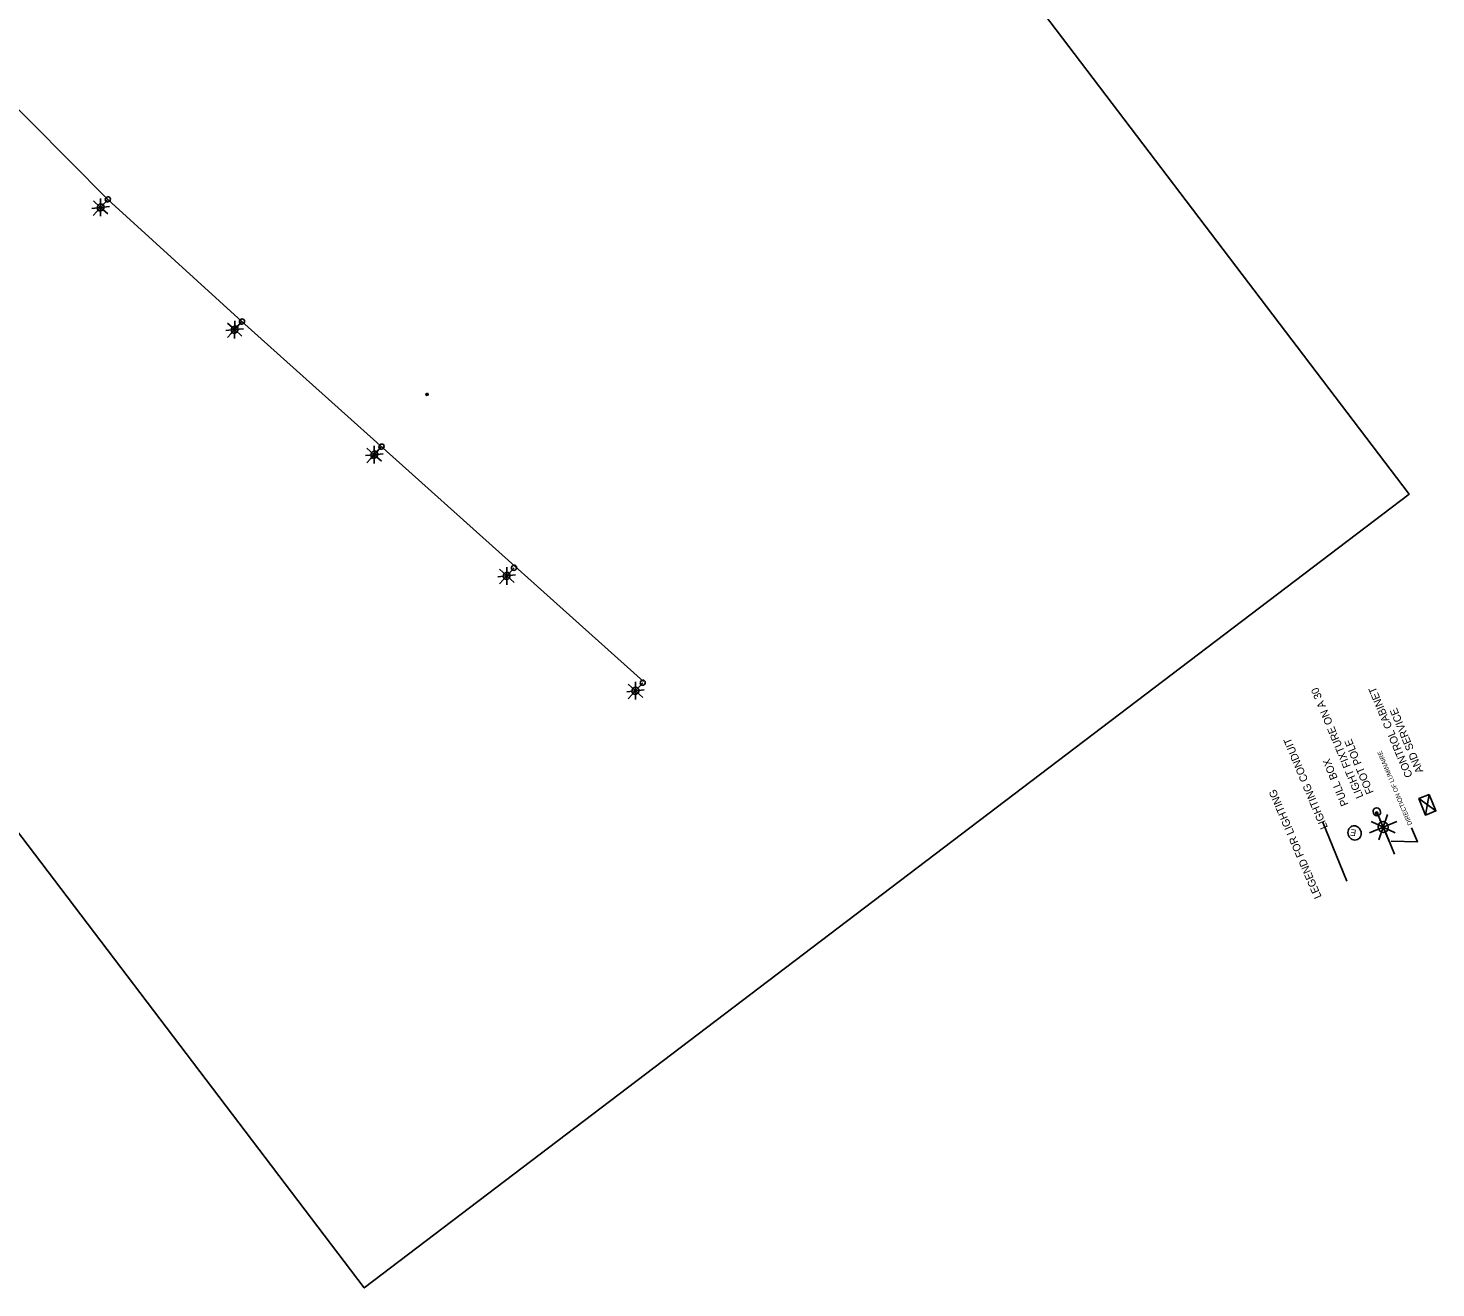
# Model space of a CAD drawing. Extents: x 1111012 to 1112403, y 616518 to 619149.
# Drawn here: x 1111840 to 1112403, y 616518 to 617023 of the extents above; entities that cross this region are included whole.
import ezdxf

# ---------------------------------------------------------------- set-up
doc = ezdxf.new("R2010")
doc.units = 0
for name, color, linetype in [('VSL-BACKGROUND', 7, 'Continuous'), ('VSL-CALCULATIONVALUES', 7, 'Continuous'), ('VSL-CONTOURS', 7, 'Continuous'), ('VSL-LUMINAIRES', 7, 'Continuous'), ('VSL-POWERZONES', 7, 'Continuous'), ('VSL-SOLIDS', 7, 'Continuous'), ('VSL-TEMPLATES', 7, 'Continuous')]:
    doc.layers.add(name, color=color, linetype=linetype)

msp = doc.modelspace()

# ---------------------------------------------------------------- linework, layer by layer
at = {"layer": 'VSL-BACKGROUND'}
msp.add_lwpolyline([(1111938.48, 617433.19), (1112392.16, 616835.98), (1111974.11, 616518.4), (1111520.42, 617115.61)], close=True, dxfattribs=at)
at = {"layer": 'VSL-CALCULATIONVALUES'}
msp.add_lwpolyline([(1112393.1, 616702.52), (1112395.46, 616696.88), (1112385, 616697.15)], dxfattribs=at)
at = {"layer": 'VSL-CONTOURS'}
msp.add_line((1112367.25, 616681.12), (1112357.47, 616704.99), dxfattribs=at)
at = {"layer": 'VSL-LUMINAIRES'}
msp.add_ellipse((1112370.34, 616700.47), major_axis=(1.11, -2.66), ratio=0.901044, dxfattribs=at)
at = {"layer": 'VSL-POWERZONES'}
for points in [[(1111999.39, 616876.47), (1111998.74, 616876.17), (1111999.06, 616875.48), (1111999.72, 616875.78)], [(1111999.39, 616876.47), (1111998.74, 616876.17), (1111999.06, 616875.48), (1111999.72, 616875.78)], [(1112379.33, 616708.93), (1112378.67, 616708.63), (1112379, 616707.95), (1112379.65, 616708.24)], [(1112379.33, 616708.93), (1112378.67, 616708.63), (1112379, 616707.95), (1112379.65, 616708.24)]]:
    msp.add_lwpolyline(points, close=True, dxfattribs=at)
for points in [[(1111999.29, 616876.43), (1111999.29, 616876.43)], [(1112379.23, 616708.89), (1112379.23, 616708.89)]]:
    msp.add_lwpolyline(points, dxfattribs=at)
at = {"layer": 'VSL-SOLIDS'}
for p, q in [((1112402.85, 616709.29), (1112396.09, 616714.19)), ((1112400.23, 616715.84), (1112398.71, 616707.63)), ((1112379.23, 616708.89), (1112381.77, 616702.81)), ((1112381.77, 616702.81), (1112383.54, 616707.86)), ((1112381.77, 616702.81), (1112376.29, 616700.52)), ((1112381.77, 616702.81), (1112376.94, 616705.1)), ((1112381.77, 616702.81), (1112380, 616697.76)), ((1112381.77, 616702.81), (1112387.24, 616705.1)), ((1112381.77, 616702.81), (1112384.31, 616696.73)), ((1112381.77, 616702.81), (1112386.6, 616700.52))]:
    msp.add_line(p, q, dxfattribs=at)
msp.add_lwpolyline([(1112400.23, 616715.84), (1112402.85, 616709.29), (1112398.71, 616707.63), (1112396.09, 616714.19)], close=True, dxfattribs=at)
msp.add_lwpolyline([(1112380.5, 616705.85), (1112383.04, 616699.77), (1112386.3, 616691.96)], dxfattribs=at)
for centre, major_axis in [((1112379.24, 616708.9), (-0.63, 1.52)), ((1112381.77, 616702.81), (-0.86, 2.08))]:
    msp.add_ellipse(centre, major_axis=major_axis, ratio=0.899857, dxfattribs=at)
at = {"layer": 'VSL-TEMPLATES'}
for p, q in [((1111868.61, 616950.79), (1111865.09, 616950.42)), ((1111868.61, 616950.79), (1111865.69, 616947.56)), ((1111868.61, 616950.79), (1111865.7, 616953.41)), ((1111870.06, 616952.41), (1111867.15, 616949.18)), ((1111868.61, 616950.79), (1111868.6, 616947.26)), ((1111868.61, 616950.79), (1111868.61, 616954.32)), ((1111871.52, 616954.02), (1111868.61, 616950.79)), ((1111868.61, 616950.79), (1111872.12, 616951.16)), ((1111868.61, 616950.79), (1111871.51, 616948.17)), ((1111922.25, 616901.9), (1111919.34, 616904.52)), ((1111922.25, 616901.9), (1111922.25, 616905.43)), ((1111925.16, 616905.13), (1111922.25, 616901.9)), ((1111922.25, 616901.9), (1111918.74, 616901.53)), ((1111922.25, 616901.9), (1111919.33, 616898.67)), ((1111923.7, 616903.51), (1111920.79, 616900.28)), ((1111922.25, 616901.9), (1111922.24, 616898.37)), ((1111922.25, 616901.9), (1111925.76, 616902.26)), ((1111922.25, 616901.9), (1111925.16, 616899.28)), ((1111978.1, 616851.84), (1111975.19, 616854.46)), ((1111979.56, 616853.46), (1111976.64, 616850.23)), ((1111978.1, 616851.84), (1111978.1, 616855.37)), ((1111981.01, 616855.07), (1111978.1, 616851.84)), ((1111978.1, 616851.84), (1111974.59, 616851.47)), ((1111978.1, 616851.84), (1111975.19, 616848.61)), ((1111978.1, 616851.84), (1111981.61, 616852.21)), ((1111978.1, 616851.84), (1111981.01, 616849.22)), ((1111978.1, 616851.84), (1111978.1, 616848.31)), ((1112031.1, 616803.34), (1112027.59, 616802.97)), ((1112031.1, 616803.34), (1112028.19, 616805.96)), ((1112031.1, 616803.34), (1112028.19, 616800.11)), ((1112032.56, 616804.96), (1112029.64, 616801.73)), ((1112031.1, 616803.34), (1112031.1, 616806.87)), ((1112034.01, 616806.57), (1112031.1, 616803.34)), ((1112031.1, 616803.34), (1112034.61, 616803.71)), ((1112031.1, 616803.34), (1112034.01, 616800.72)), ((1112031.1, 616803.34), (1112031.1, 616799.81)), ((1112082.6, 616757.34), (1112079.69, 616759.96)), ((1112084.06, 616758.96), (1112081.14, 616755.73)), ((1112082.6, 616757.34), (1112082.6, 616760.87)), ((1112085.51, 616760.57), (1112082.6, 616757.34)), ((1112082.6, 616757.34), (1112086.11, 616757.71)), ((1112082.6, 616757.34), (1112079.09, 616756.97)), ((1112082.6, 616757.34), (1112079.69, 616754.11)), ((1112082.6, 616757.34), (1112085.51, 616754.72)), ((1112082.6, 616757.34), (1112082.6, 616753.81))]:
    msp.add_line(p, q, dxfattribs=at)
for points in [[(1111871.52, 616954.02), (1111825.35, 617000.34), (1111782.47, 617055.37), (1111743.19, 617122.65), (1111712.13, 617195.8), (1111694.38, 617237.58)], [(1112085.77, 616761.06), (1111925.16, 616905.13), (1111871.52, 616954.02)]]:
    msp.add_lwpolyline(points, dxfattribs=at)
for centre, major_axis in [((1111871.52, 616954.02), (0.729, 0.805)), ((1111868.61, 616950.79), (1, 1.1)), ((1111925.17, 616905.12), (0.729, 0.805)), ((1111922.25, 616901.9), (1, 1.1)), ((1111978.1, 616851.84), (1, 1.1)), ((1111981.02, 616855.07), (0.729, 0.805)), ((1112031.1, 616803.34), (1, 1.1)), ((1112034.02, 616806.57), (0.729, 0.805)), ((1112082.6, 616757.34), (1, 1.1)), ((1112085.52, 616760.57), (0.729, 0.805))]:
    msp.add_ellipse(centre, major_axis=major_axis, ratio=0.899857, dxfattribs=at)

# ---------------------------------------------------------------- texts
at = {"layer": 'VSL-CALCULATIONVALUES'}
for s, height, rotation, p in [('LIGHT FIXTURE ON A 30 ', 3.0627, 112.638, (1112373.92, 616715.03)), ('CONTROL CABINET ', 3.0627, 112.7167, (1112393.65, 616723.36)), ('AND SERVICE', 3.0627, 112.7167, (1112397.89, 616725.14)), ('LIGHTING CONDUIT', 3.0627, 112.638, (1112359.69, 616702.71)), ('FOOT POLE ', 3.063, 112.638, (1112378.02, 616716.74)), ('PULL BOX', 3.063, 112.2855, (1112367.94, 616711.92)), ('DIRECTION OF LUMINAIRE', 1.7989, 112.7167, (1112393.43, 616703.96)), ('LEGEND FOR LIGHTING', 3.0627, 113.1702, (1112357.22, 616674.92))]:
    msp.add_text(s, height=height, rotation=rotation, dxfattribs=at).set_placement(p)
at = {"layer": 'VSL-LUMINAIRES'}
msp.add_text('E', height=2.58, rotation=169.9264, dxfattribs=at).set_placement((1112371.15, 616701.64))

doc.saveas('drawing.dxf')
